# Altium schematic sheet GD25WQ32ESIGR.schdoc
size 127 x 101 mm
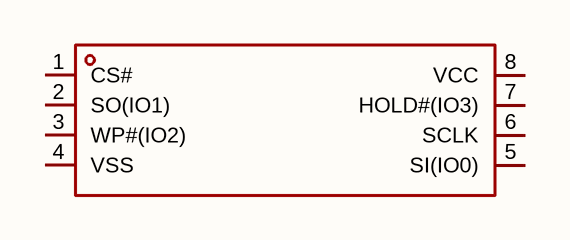
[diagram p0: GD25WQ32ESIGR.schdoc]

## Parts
U?  gd25wq32esigr  [SOP-8_L5.3-W5.2-P1.27-LS7.9-BL]  (value not drawn)

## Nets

Not connected (* = marked no-connect by the designer): U? 1(CS#) 2(SO(IO1)) 3(WP#(IO2)) 4(VSS) 5(SI(IO0)) 6(SCLK) 7(HOLD#(IO3)) 8(VCC)

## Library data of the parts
U? = gd25wq32esigr: 接口类型:SPI;存储容量:32Mbit;时钟频率(fc):104MHz;; Manufacturer: GigaDevice(兆易创新); AddInBom: yes; ModelId: b3bace262c53465a9e6115a2e0c7b3cc; ModelTransform: 205.905,311.023,0,0,0,0,0,0,0; Interface: SPI; Memory Size: 32Mbit; Clock Frequency: 104MHz; Voltage - Supply: 1.65V~3.6V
